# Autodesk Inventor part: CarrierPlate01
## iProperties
Created: 2008-02
Part Number: CarrierPlate01
Document SubType Name: Modeling
Designer: grh
Density: 1 g/cm^3
Author: grh
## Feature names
1. Extrusion1
